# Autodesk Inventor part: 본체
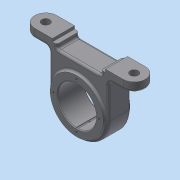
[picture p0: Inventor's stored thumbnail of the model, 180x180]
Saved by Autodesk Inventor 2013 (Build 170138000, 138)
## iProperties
Created: 2019-05
Part Number: 본체
Material: 일반
Document SubType Name: Modeling
Designer: dgall
Density: 1 g/cm^3
Author: dgall
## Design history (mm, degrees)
sketch "스케치1"
  geometry: C1 r 40 at (0, 0); C2 r 36 at (0, 0); C3 r 26 at (0, 0); 1 further point
  constraints: 3 centre point, 3 coincident
  dimensions: "d0" = 40 radius of C1; "d1" = 36 radius of C2; "d2" = 26 radius of C3
extrude "돌출1" new body sketch "스케치1" stored distance "d3" = 36; taper "d4" = 0 deg
extrude "돌출2" join sketch "스케치1" stored distance "d5" = 30; taper "d6" = 0 deg
sketch "스케치2"
  geometry: L1 (40, 0)-(40, 48); L2 (40, 48)-(75, 48); L3 (75, 48)-(75, 60); L4 (75, 60)-(36, 60); L5 (36, 60)-(36, 56); L6 (36, 56)-(30, 56); L7 (30, 56)-(30, 50); L8 (30, 50)-(-30, 50); L9 (-30, 50)-(-30, 56); L10 (-30, 56)-(-36, 56); L11 (-36, 56)-(-36, 60); L12 (-36, 60)-(-75, 60); L13 (-75, 60)-(-75, 48); L14 (-75, 48)-(-40, 48); L15 (-40, 48)-(-40, 0); C1 r 26 at (0, 0) reference; A1 r 40 centre (0, 0) between (40, 0) and (-40, 0) reference; 2 further points
  constraints: 30 end point, 8 vertical, 7 horizontal, 6 equal length, 2 point on circle, 1 midpoint, 1 tangent, 1 vertical alignment
  dimensions: "d7" = 4 distance of L4.end L5.end; "d8" = 10 distance between parallel lines of L8 L4; "d9" = 12 distance of L2.end L3.end; "d10" = 60 distance from line of point (0, 0) L4; "d11" = 60 distance of L7.end L8.end; "d12" = 72 distance between parallel lines of L11 L5; "d13" = 150 distance between parallel lines of L13 L3
extrude "돌출3" join sketch "스케치2" stored distance "d14" = 30; taper "d15" = 0 deg
fillet "모깎기1" dims "d16" = 15
fillet "모깎기2" dims "d17" = 6
fillet "모깎기3" dims "d18" = 3
sketch "스케치3"
  geometry: C1 r 26 at (0, 0) reference; 1 further point
  constraints: 1 vertical alignment
  dimensions: "d19" = 31 distance of C1.centre point (0, 31)
hole "구멍1" sketch "스케치3" at (0, 31) diameter "d20" = 3.242; stored, may be unused: countersink angle "d24" = 90 deg, drill point angle "d26" = 118 deg; dims "d21" = 6, "d22" = 4, "d23" = 2, "d25" = 8
sketch "스케치4"
  geometry: C1 r 9 at (14, 12); A1 r 12 centre (14, 12) between (14, 0) and (14, 24) reference; 1 further point
  constraints: 1 centre point, 1 coincident
  dimensions: "d30" = 9 radius of C1
extrude "돌출4" join sketch "스케치4" distance "d31" = 3; taper "d32" = 0 deg
hole "구멍2" diameter "d35" = 11; stored, may be unused: countersink angle "d39" = 90 deg, drill point angle "d41" = 118 deg; dims "d33" = 10, "d34" = 10, "d36" = 11, "d37" = 4, "d38" = 2, "d40" = 8
fillet "모깎기4" dims "d42" = 3
node "작업 평면1"
sketch "스케치5"
  geometry: C1 r 3.5 at (0, 0); 1 further point
  constraints: 1 centre point, 1 coincident
  dimensions: "d43" = 3.5 radius of C1
extrude "돌출5" cut sketch "스케치5" distance "d44" = 1; taper "d45" = 0 deg
hole "구멍3" diameter "d48" = 4.917; stored, may be unused: countersink angle "d52" = 90 deg, drill point angle "d54" = 118 deg; dims "d49" = 7, "d50" = 4, "d51" = 2, "d53" = 9, "d68" = 10, "d69" = 10
sketch "스케치6"
  geometry: C1 r 3.5 at (0, 0) reference; C2 r 1 at (0, 0)
  constraints: 1 centre point, 1 coincident
  dimensions: "d55" = 1 radius of C2
extrude "돌출6" cut sketch "스케치6" stored distance "d56" = 1; taper "d57" = 0 deg
fillet "모깎기5" dims "d58" = 3
sketch "스케치7"
  geometry: C1 r 1.621 at (0, 31) reference; C2 r 1.5 at (0, 26); 1 further point
  constraints: 2 vertical alignment, 1 centre point, 1 other
  dimensions: "d59" = 1.5 radius of C2
extrude "돌출7" cut sketch "스케치7" stored distance "d60" = 1; taper "d61" = 0 deg
sketch "스케치8"
  geometry: L1 (-36, -60)-(-60, -60) reference; L2 (-60, -60)-(-60, -51) reference; L3 (-60, -51)-(-46, -51) reference; L4 (-37, -42)-(-37, -12.329) reference; L5 (37, -12.329)-(37, -42) reference; L6 (46, -51)-(60, -51) reference; L7 (60, -51)-(60, -60) reference; L8 (60, -60)-(36, -60) reference; L9 (36, -60)-(36, -56) reference; L10 (36, -56)-(33, -56) reference; L11 (33, -56)-(33, -53) reference; L12 (27, -47)-(-27, -47) reference; L13 (-33, -53)-(-33, -56) reference; L14 (-33, -56)-(-36, -56) reference; L15 (-36, -56)-(-36, -60) reference; L16 (-27, -50)-(27, -50) reference; C1 r 1.621 at (31, 0) reference; C2 r 1.621 at (0, -31) reference; C3 r 1.621 at (-31, 0) reference; C4 r 1.621 at (0, 31) reference; A1 r 39 centre (0, 0) between (-37, -12.329) and (37, -12.329) reference; A2 r 1.5 centre (0, 26) between (1.499, 25.957) and (-1.499, 25.957) reference; A3 r 26 centre (0, 0) between (-1.499, 25.957) and (1.499, 25.957) reference; A4 r 9 centre (-46, -42) between (-46, -51) and (-37, -42) reference; A5 r 37.607 centre (0, 0) between (37.607, 0) and (-37.607, 0) reference; A6 r 9 centre (46, -42) between (37, -42) and (46, -51) reference; A7 r 6 centre (27, -53) between (33, -53) and (27, -47) reference; A8 r 6 centre (-27, -53) between (-27, -47) and (-33, -53) reference; A9 r 39 centre (0, 0) between (-37, -12.329) and (37, -12.329) reference; 1 further point
  constraints: 1 vertical alignment, 3 other
  dimensions: "d62" = 7 distance from line of L16 point (0, -43)
feature "엠보싱1" sketch "스케치8" dims "d63" = 0.5, "d64" = 0
chamfer "모따기1" distance "d65" = 1; stored, may be unused: second distance "d66" = 2, angle "d67" = 45 deg
node "솔리드1"
pattern_circular "원형 패턴1" dims angle "d28" = 360 deg
mirror "대칭1"
mirror "대칭2"
mirror "대칭3"
node "절단 모서리 투영1"
node "절단 모서리 투영2"
